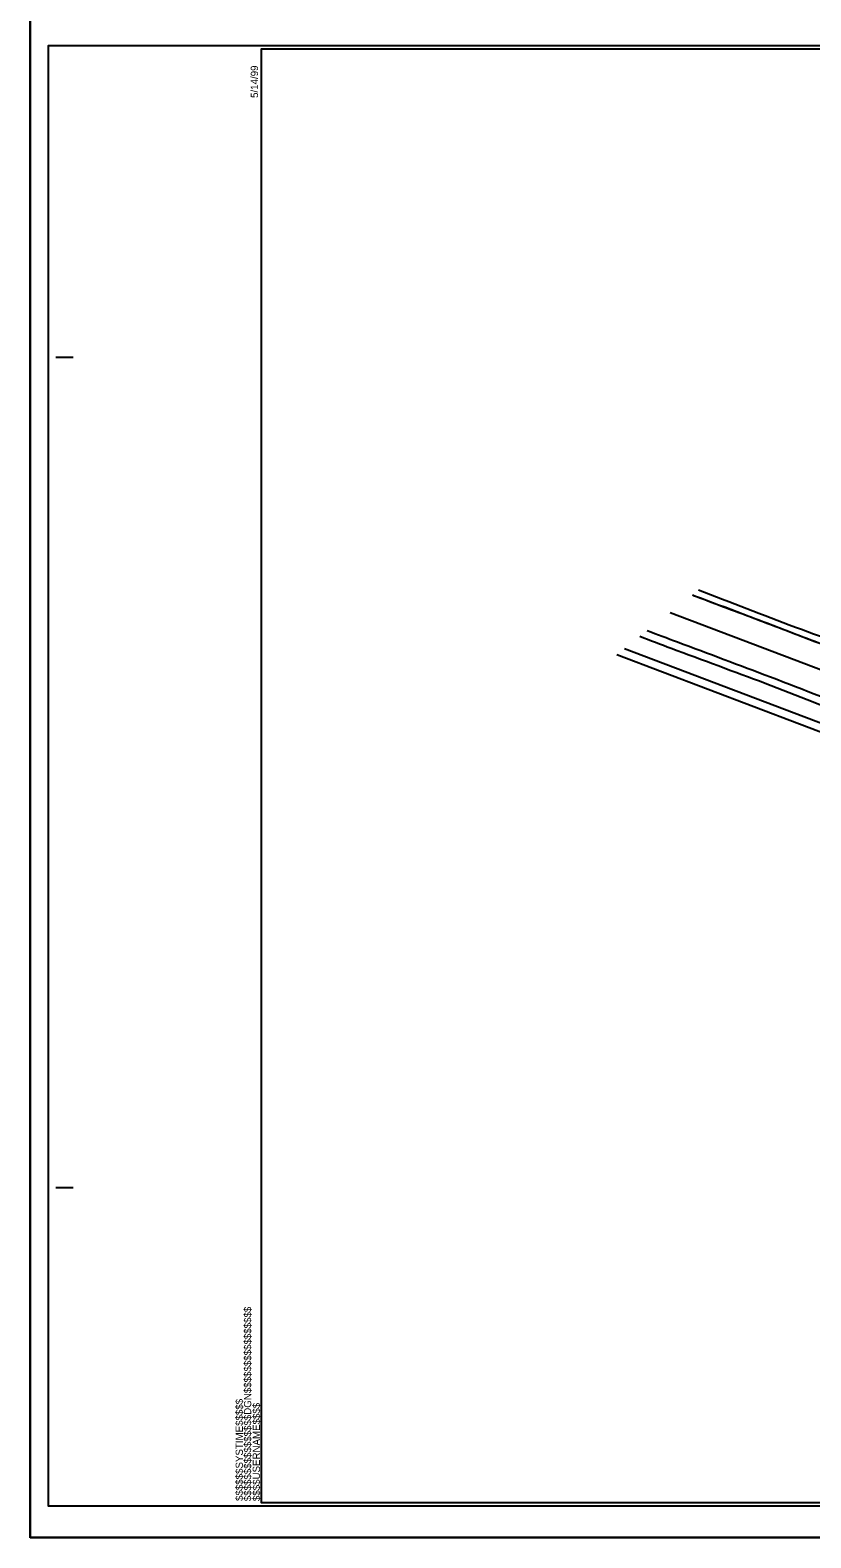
# Model space of a CAD drawing. Extents: x 573813 to 575363, y -54752 to -53123.
# Drawn here: x 574669.7 to 574782.6, y -54663.7 to -54445.8 of the extents above; entities that cross this region are included whole.
import ezdxf

# ---------------------------------------------------------------- set-up
doc = ezdxf.new("R2010")
doc.units = 0
for name, color, linetype in [('Exist CMT EOP', 7, 'Continuous'), ('Prop EOT', 7, 'Continuous'), ('Prop Horizontal Alignment', 7, 'Continuous'), ('Prop Paved Shoulder', 7, 'Continuous'), ('Sheet Border Standard 30in CELL', 7, 'Continuous'), ('Sheet Cutting Line CELL', 7, 'Continuous'), ('Sheet Plot Border Inside CELL', 7, 'Continuous'), ('Sheet Plot Border Outside CELL', 7, 'Continuous')]:
    doc.layers.add(name, color=color, linetype=linetype)

msp = doc.modelspace()

# ---------------------------------------------------------------- linework, layer by layer
at = {"layer": 'Exist CMT EOP'}
for points in [[(574913.91, -54582.47), (574905.37, -54579.27), (574892.21, -54574.27), (574877.75, -54568.85), (574863.65, -54563.66), (574849.2, -54558.16), (574835.56, -54552.94), (574822.1, -54547.9), (574808.04, -54542.42), (574794.3, -54537.21), (574780.37, -54532.09), (574766.36, -54526.71)], [(574765.48, -54527.41), (574765.78, -54527.52), (574779.74, -54532.79), (574793.48, -54538.06), (574807.46, -54543.39), (574821.47, -54548.76), (574835.96, -54554.18), (574850.01, -54559.51), (574864.07, -54564.79), (574878.2, -54570.12), (574891.53, -54575.2), (574905.99, -54580.54), (574913.01, -54583.17)], [(574757.88, -54533.38), (574762.42, -54535.1), (574776.01, -54540.16), (574789.83, -54545.55), (574804.17, -54551.04), (574818.28, -54556.38), (574832.14, -54561.65), (574846.05, -54566.95), (574860.34, -54572.32), (574875.56, -54578.1), (574889.01, -54583.16), (574902.5, -54588.19), (574905.31, -54589.23)], [(574758.94, -54532.55), (574763.31, -54534.19), (574776.79, -54539.25), (574791.23, -54544.84), (574804.88, -54550.03), (574818.88, -54555.25), (574832.97, -54560.72), (574847.44, -54566.13), (574861.46, -54571.38), (574875.13, -54576.5), (574889.09, -54581.73), (574903.52, -54587.19), (574906.48, -54588.31)]]:
    msp.add_spline(points, degree=3, dxfattribs=at)
at = {"layer": 'Prop EOT'}
msp.add_line((574755.67, -54535.12), (574838.9, -54566.78), dxfattribs=at)
msp.add_open_spline([(574765.48, -54527.41), (574765.58, -54527.45), (574765.68, -54527.48), (574765.78, -54527.52), (574770.43, -54529.28), (574775.09, -54531.02), (574779.74, -54532.79), (574784.33, -54534.53), (574788.9, -54536.31), (574793.48, -54538.06), (574798.14, -54539.84), (574802.8, -54541.61), (574807.46, -54543.39), (574812.13, -54545.17), (574816.79, -54546.98), (574821.47, -54548.76), (574826.29, -54550.59), (574831.14, -54552.35), (574835.96, -54554.18), (574840.65, -54555.95), (574845.32, -54557.75), (574850.01, -54559.51), (574854.69, -54561.28), (574859.38, -54563.03), (574864.07, -54564.79), (574868.78, -54566.56), (574873.49, -54568.34), (574878.2, -54570.12), (574882.65, -54571.8), (574887.08, -54573.52), (574891.53, -54575.2), (574896.34, -54577), (574901.17, -54578.74), (574905.99, -54580.54), (574908.33, -54581.42), (574910.67, -54582.3), (574913.01, -54583.17)], degree=3, dxfattribs=at)
at = {"layer": 'Prop Horizontal Alignment'}
msp.add_line((574762.27, -54529.93), (574870.34, -54571.03), dxfattribs=at)
msp.add_line((574762.27, -54529.93), (574870.34, -54571.03), dxfattribs=at)
at = {"layer": 'Prop Paved Shoulder'}
msp.add_line((574754.57, -54535.99), (574819.22, -54560.58), dxfattribs=at)
at = {"layer": 'Sheet Border Standard 30in CELL'}
for p, q in [((574703.33, -54448.54), (574703.33, -54448.54)), ((574673.43, -54493.04), (574675.93, -54493.04)), ((574673.43, -54613.04), (574675.93, -54613.04))]:
    msp.add_line(p, q, dxfattribs=at)
msp.add_lwpolyline([(575003.13, -54448.54), (574703.13, -54448.54), (574703.13, -54658.54), (575003.13, -54658.54)], close=True, dxfattribs=at)
at = {"layer": 'Sheet Cutting Line CELL'}
for p, q in [((574669.73, -54663.66), (574669.73, -54443.54)), ((574669.73, -54443.54), (574669.73, -54663.54)), ((574669.73, -54663.54), (575006.53, -54663.54)), ((575006.71, -54663.66), (574669.73, -54663.66))]:
    msp.add_line(p, q, dxfattribs=at)
at = {"layer": 'Sheet Plot Border Inside CELL'}
msp.add_lwpolyline([(575005.63, -54448.03), (574672.33, -54448.03), (574672.33, -54659.05), (575005.63, -54659.05)], close=True, dxfattribs=at)
at = {"layer": 'Sheet Plot Border Outside CELL'}
msp.add_lwpolyline([(575006.53, -54443.54), (574669.73, -54443.54), (574669.73, -54663.54), (575006.53, -54663.54)], close=True, dxfattribs=at)

# ---------------------------------------------------------------- texts
at = {"layer": 'Sheet Border Standard 30in CELL'}
for s, p in [('5/14/99', (574702.68, -54455.58)), ('$$$$$$$$$$$$$$$$DGN$$$$$$$$$$$$$$$$', (574701.7, -54658.37)), ('$$$$$$SYSTIME$$$$$', (574700.49, -54658.33)), ('$$$$USERNAME$$$$', (574702.96, -54658.35))]:
    msp.add_text(s, height=1.05, rotation=90, dxfattribs=at).set_placement(p)

doc.saveas('drawing.dxf')
